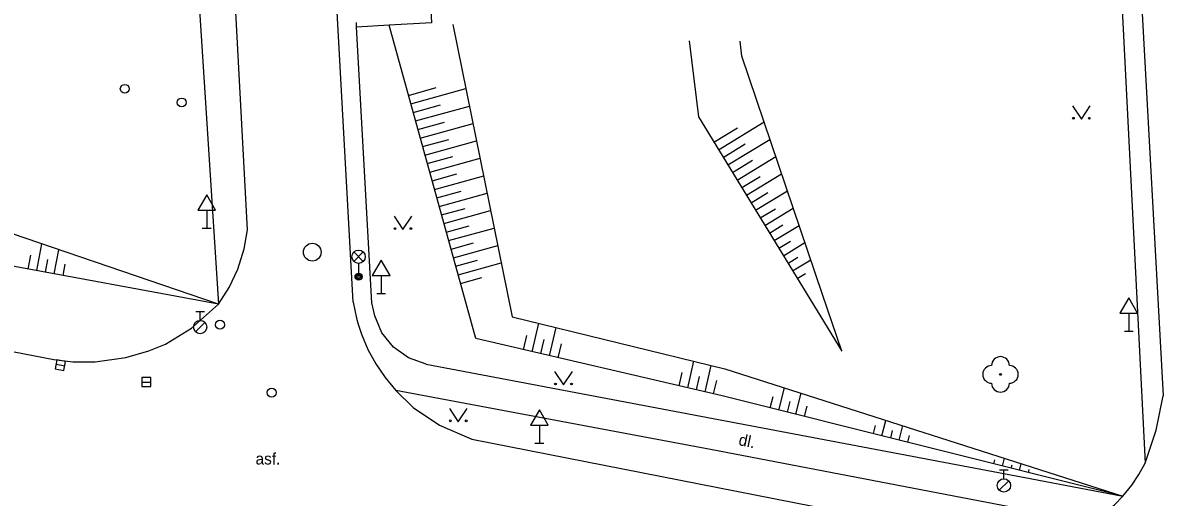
# Model space of a CAD drawing. Extents: x -599951 to -598963, y -1164095 to -1162939.
# Drawn here: x -599434.3 to -599370, y -1163132 to -1163105.2 of the extents above; entities that cross this region are included whole.
import ezdxf

# ---------------------------------------------------------------- set-up
doc = ezdxf.new("R2010")
doc.units = 0
for name, color, linetype in [('Level 10', 7, 'Continuous'), ('Level 11', 7, 'Continuous'), ('Level 14', 7, 'Continuous'), ('Level 15', 7, 'Continuous'), ('Level 22', 7, 'Continuous'), ('Level 27', 7, 'Continuous'), ('Level 28', 7, 'Continuous'), ('Level 31', 7, 'Continuous'), ('Level 33', 7, 'Continuous'), ('Level 34', 7, 'Continuous'), ('Level 36', 7, 'Continuous'), ('Level 40', 7, 'Continuous')]:
    doc.layers.add(name, color=color, linetype=linetype)

msp = doc.modelspace()

# ---------------------------------------------------------------- linework, layer by layer
at = {"layer": 'Level 10'}
for points in [[(-599421.64, -1163116.9), (-599425.1, -1163052.38), (-599428, -1162999.57)], [(-599415.69, -1163120.97), (-599422.36, -1163000.03)], [(-599372.62, -1163079.04), (-599370.03, -1163126.26)], [(-599575.76, -1163096.42), (-599468.94, -1163117.19), (-599432.56, -1163124.21)], [(-599422.18, -1163119.11), (-599421.831, -1163117.966), (-599421.64, -1163116.9)], [(-599423.27, -1163121.1), (-599422.678, -1163120.153), (-599422.18, -1163119.11)], [(-599423.27, -1163121.1), (-599424.79, -1163122.44)], [(-599415.69, -1163120.97), (-599415.502, -1163121.885), (-599415.4, -1163122.21), (-599415.224, -1163122.778), (-599414.86, -1163123.64), (-599414.414, -1163124.46), (-599413.889, -1163125.233), (-599413.29, -1163125.95)], [(-599426.27, -1163123.35), (-599424.79, -1163122.44)], [(-599428.5, -1163124.1), (-599427.2, -1163123.72), (-599426.27, -1163123.35)], [(-599430.23, -1163124.35), (-599428.5, -1163124.1)], [(-599432.56, -1163124.21), (-599431.48, -1163124.34), (-599430.23, -1163124.35)], [(-599413.29, -1163125.95), (-599412.3, -1163126.91), (-599410.82, -1163127.91), (-599408.99, -1163128.7), (-599378.01, -1163134.79)], [(-599370.42, -1163128.19), (-599370.03, -1163126.26)], [(-599371.05, -1163130.05), (-599370.42, -1163128.19)], [(-599372.3, -1163131.92), (-599371.797, -1163131.286), (-599371.411, -1163130.7), (-599371.05, -1163130.05)], [(-599374.09, -1163133.4), (-599373.41, -1163132.94), (-599372.77, -1163132.4), (-599372.3, -1163131.92)]]:
    msp.add_lwpolyline(points, dxfattribs=at)
at = {"layer": 'Level 11'}
for points in [[(-599372.7, -1163097.42), (-599371.05, -1163130.05)], [(-599411.57, -1163099.7), (-599411.27, -1163105.24)], [(-599424.37, -1163104.22), (-599423.27, -1163121.1)], [(-599415.49, -1163105.47), (-599415.5, -1163105.22)], [(-599413.66, -1163105.37), (-599415.49, -1163105.47)], [(-599414.63, -1163121.02), (-599415.49, -1163105.47)], [(-599411.27, -1163105.24), (-599413.66, -1163105.37)], [(-599411.58, -1163124.47), (-599412.561, -1163124.117), (-599413.41, -1163123.512), (-599414.064, -1163122.699), (-599414.473, -1163121.74), (-599414.63, -1163121.02)], [(-599411.58, -1163124.47), (-599377.13, -1163130.99), (-599372.3, -1163131.92)], [(-599374.09, -1163133.4), (-599395.55, -1163129.28), (-599413.29, -1163125.95)]]:
    msp.add_lwpolyline(points, dxfattribs=at)
at = {"layer": 'Level 14'}
for points in [[(-599423.27, -1163121.1), (-599435.72, -1163118.79), (-599451.15, -1163116.24), (-599463.66, -1163113.69), (-599489.16, -1163110.88), (-599508.36, -1163107.11), (-599527.75, -1163103.16), (-599545.37, -1163099.59), (-599551.42, -1163096.73)], [(-599408.78, -1163123.03), (-599413.66, -1163105.37)], [(-599410.06, -1163105.33), (-599406.72, -1163121.81)], [(-599396.75, -1163106.25), (-599396.22, -1163110.54)], [(-599389.24, -1163120.54), (-599393.78, -1163107.12), (-599393.87, -1163106.26)], [(-599423.27, -1163121.1), (-599437.28, -1163116.31), (-599449.05, -1163113.93), (-599455.91, -1163113), (-599472.24, -1163108.69)], [(-599396.22, -1163110.54), (-599388.15, -1163123.74)], [(-599388.15, -1163123.74), (-599389.24, -1163120.54)], [(-599406.72, -1163121.81), (-599394.73, -1163124.73), (-599372.3, -1163131.92)], [(-599372.3, -1163131.92), (-599394.88, -1163126.26), (-599408.78, -1163123.03)]]:
    msp.add_lwpolyline(points, dxfattribs=at)
at = {"layer": 'Level 15'}
for points in [[(-599412.57, -1163109.32), (-599411, -1163108.88)], [(-599412.44, -1163109.8), (-599409.33, -1163108.94)], [(-599412.31, -1163110.28), (-599410.77, -1163109.85)], [(-599412.17, -1163110.76), (-599409.13, -1163109.92)], [(-599412.04, -1163111.24), (-599410.54, -1163110.83)], [(-599411.91, -1163111.73), (-599408.93, -1163110.9)], [(-599395.35, -1163111.96), (-599394.02, -1163111.15)], [(-599395.09, -1163112.39), (-599392.53, -1163110.82)], [(-599411.77, -1163112.21), (-599410.3, -1163111.8)], [(-599411.64, -1163112.69), (-599408.73, -1163111.88)], [(-599394.57, -1163113.24), (-599392.2, -1163111.8)], [(-599394.83, -1163112.82), (-599393.59, -1163112.06)], [(-599411.51, -1163113.17), (-599410.07, -1163112.77)], [(-599411.37, -1163113.65), (-599408.53, -1163112.87)], [(-599394.31, -1163113.67), (-599393.17, -1163112.98)], [(-599394.05, -1163114.1), (-599391.87, -1163112.77)], [(-599411.24, -1163114.13), (-599409.84, -1163113.75)], [(-599411.11, -1163114.62), (-599408.33, -1163113.85)], [(-599393.78, -1163114.52), (-599392.74, -1163113.89)], [(-599393.52, -1163114.95), (-599391.54, -1163113.74)], [(-599410.97, -1163115.1), (-599409.6, -1163114.72)], [(-599410.84, -1163115.58), (-599408.13, -1163114.83)], [(-599393.26, -1163115.38), (-599392.32, -1163114.8)], [(-599393, -1163115.8), (-599391.21, -1163114.71)], [(-599410.71, -1163116.06), (-599409.37, -1163115.69)], [(-599410.57, -1163116.54), (-599407.94, -1163115.81)], [(-599392.74, -1163116.23), (-599391.89, -1163115.71)], [(-599392.48, -1163116.66), (-599390.88, -1163115.68)], [(-599410.44, -1163117.03), (-599409.14, -1163116.67)], [(-599410.31, -1163117.51), (-599407.74, -1163116.8)], [(-599392.22, -1163117.08), (-599391.47, -1163116.62)], [(-599391.96, -1163117.51), (-599390.55, -1163116.65)], [(-599433.51, -1163119.2), (-599433.23, -1163117.69)], [(-599410.17, -1163117.99), (-599408.91, -1163117.64)], [(-599391.7, -1163117.94), (-599391.04, -1163117.54)], [(-599391.44, -1163118.36), (-599390.22, -1163117.62)], [(-599434, -1163119.11), (-599433.85, -1163118.32)], [(-599432.53, -1163119.38), (-599432.27, -1163118.02)], [(-599410.04, -1163118.47), (-599407.54, -1163117.78)], [(-599433.02, -1163119.29), (-599432.89, -1163118.57)], [(-599432.03, -1163119.47), (-599431.92, -1163118.83)], [(-599409.91, -1163118.95), (-599408.67, -1163118.61)], [(-599409.77, -1163119.44), (-599407.34, -1163118.76)], [(-599391.18, -1163118.79), (-599390.62, -1163118.45)], [(-599390.92, -1163119.22), (-599389.89, -1163118.59)], [(-599409.64, -1163119.92), (-599408.44, -1163119.59)], [(-599390.66, -1163119.64), (-599390.19, -1163119.36)], [(-599405.59, -1163123.77), (-599405.22, -1163122.17)], [(-599406.08, -1163123.66), (-599405.9, -1163122.86)], [(-599404.62, -1163124), (-599404.25, -1163122.41)], [(-599405.11, -1163123.88), (-599404.92, -1163123.09)], [(-599404.13, -1163124.11), (-599403.95, -1163123.32)], [(-599396.83, -1163125.81), (-599396.48, -1163124.3)], [(-599395.85, -1163126.03), (-599395.51, -1163124.54)], [(-599397.31, -1163125.69), (-599397.14, -1163124.94)], [(-599396.34, -1163125.92), (-599396.17, -1163125.17)], [(-599395.37, -1163126.15), (-599395.19, -1163125.4)], [(-599391.7, -1163127.06), (-599391.38, -1163125.8)], [(-599392.18, -1163126.94), (-599392.02, -1163126.29)], [(-599391.21, -1163127.18), (-599391.06, -1163126.57)], [(-599390.73, -1163127.3), (-599390.43, -1163126.11)], [(-599390.24, -1163127.42), (-599390.1, -1163126.84)], [(-599386.36, -1163128.39), (-599386.25, -1163127.94)], [(-599385.88, -1163128.52), (-599385.66, -1163127.64)], [(-599384.91, -1163128.76), (-599384.7, -1163127.94)], [(-599385.39, -1163128.64), (-599385.29, -1163128.21)], [(-599384.42, -1163128.88), (-599384.33, -1163128.49)], [(-599379.57, -1163130.1), (-599379.52, -1163129.86)], [(-599379.09, -1163130.22), (-599378.98, -1163129.78)], [(-599378.6, -1163130.34), (-599378.55, -1163130.14)], [(-599378.12, -1163130.46), (-599378.03, -1163130.08)], [(-599377.63, -1163130.58), (-599377.59, -1163130.41)]]:
    msp.add_lwpolyline(points, dxfattribs=at)
at = {"layer": 'Level 22'}
msp.add_circle((-599379.2, -1163125.05), 0.05, dxfattribs=at)
for centre, start, end in [((-599379.2, -1163124.55), 0, 180), ((-599379.7, -1163125.05), 90, 270), ((-599378.7, -1163125.05), 270, 90), ((-599379.2, -1163125.55), 180, 0)]:
    msp.add_arc(centre, 0.5, start, end, dxfattribs=at)
at = {"layer": 'Level 27'}
for p, q in [((-599432.435, -1163124.483), (-599431.945, -1163124.577)), ((-599427.59, -1163125.48), (-599427.09, -1163125.48))]:
    msp.add_line(p, q, dxfattribs=at)
for points in [[(-599432.483, -1163124.728), (-599431.992, -1163124.823), (-599431.897, -1163124.332), (-599432.388, -1163124.237)], [(-599427.59, -1163125.73), (-599427.09, -1163125.73), (-599427.09, -1163125.23), (-599427.59, -1163125.23)]]:
    msp.add_lwpolyline(points, close=True, dxfattribs=at)
msp.add_circle((-599417.99, -1163118.16), 0.5, dxfattribs=at)
at = {"layer": 'Level 28'}
for p, q in [((-599424.56, -1163121.505), (-599424.06, -1163121.505)), ((-599424.31, -1163122.005), (-599424.31, -1163121.505)), ((-599424.568, -1163122.652), (-599424.038, -1163122.122)), ((-599379.26, -1163130.435), (-599378.76, -1163130.435)), ((-599379.01, -1163130.935), (-599379.01, -1163130.435)), ((-599379.268, -1163131.582), (-599378.738, -1163131.052))]:
    msp.add_line(p, q, dxfattribs=at)
for centre, radius in [((-599424.31, -1163122.38), 0.375), ((-599423.19, -1163122.25), 0.25), ((-599379.01, -1163131.31), 0.375)]:
    msp.add_circle(centre, radius, dxfattribs=at)
at = {"layer": 'Level 31'}
for centre in [(-599428.56, -1163108.95), (-599425.35, -1163109.72), (-599420.28, -1163126.08)]:
    msp.add_circle(centre, 0.25, dxfattribs=at)
at = {"layer": 'Level 33'}
for p, q in [((-599415.645, -1163118.68), (-599415.115, -1163118.15)), ((-599415.645, -1163118.15), (-599415.115, -1163118.68)), ((-599415.38, -1163118.79), (-599415.38, -1163119.54))]:
    msp.add_line(p, q, dxfattribs=at)
for centre, radius in [((-599415.38, -1163118.415), 0.375), ((-599415.38, -1163119.54), 0.2), ((-599415.38, -1163119.54), 0.145), ((-599415.38, -1163119.54), 0.0876)]:
    msp.add_circle(centre, radius, dxfattribs=at)
at = {"layer": 'Level 34'}
for p, q in [((-599423.94, -1163115.792), (-599423.94, -1163116.81)), ((-599424.19, -1163116.81), (-599423.69, -1163116.81)), ((-599414.11, -1163119.472), (-599414.11, -1163120.49)), ((-599414.36, -1163120.49), (-599413.86, -1163120.49)), ((-599371.97, -1163121.592), (-599371.97, -1163122.61)), ((-599372.22, -1163122.61), (-599371.72, -1163122.61)), ((-599405.19, -1163127.912), (-599405.19, -1163128.93)), ((-599405.44, -1163128.93), (-599404.94, -1163128.93))]:
    msp.add_line(p, q, dxfattribs=at)
for points in [[(-599424.44, -1163115.792), (-599423.44, -1163115.792), (-599423.94, -1163114.926)], [(-599414.61, -1163119.472), (-599413.61, -1163119.472), (-599414.11, -1163118.606)], [(-599372.47, -1163121.592), (-599371.47, -1163121.592), (-599371.97, -1163120.726)], [(-599405.69, -1163127.912), (-599404.69, -1163127.912), (-599405.19, -1163127.046)]]:
    msp.add_lwpolyline(points, close=True, dxfattribs=at)
at = {"layer": 'Level 36'}
for points in [[(-599375.14, -1163109.91), (-599374.64, -1163110.66), (-599374.14, -1163109.91)], [(-599413.38, -1163116.13), (-599412.88, -1163116.88), (-599412.38, -1163116.13)], [(-599404.33, -1163124.89), (-599403.83, -1163125.64), (-599403.33, -1163124.89)], [(-599410.26, -1163126.97), (-599409.76, -1163127.72), (-599409.26, -1163126.97)]]:
    msp.add_lwpolyline(points, dxfattribs=at)
for centre in [(-599375.09, -1163110.61), (-599374.191, -1163110.61), (-599413.33, -1163116.83), (-599412.431, -1163116.83), (-599404.28, -1163125.59), (-599403.381, -1163125.59), (-599410.21, -1163127.67), (-599409.311, -1163127.67)]:
    msp.add_circle(centre, 0.05, dxfattribs=at)

# ---------------------------------------------------------------- texts
at = {"layer": 'Level 40'}
msp.add_text('dl.', height=0.65, rotation=348.44, dxfattribs=at).set_placement((-599394, -1163129.03))
msp.add_text('asf.', height=0.65, dxfattribs=at).set_placement((-599421.19, -1163130.13))

doc.saveas('drawing.dxf')
